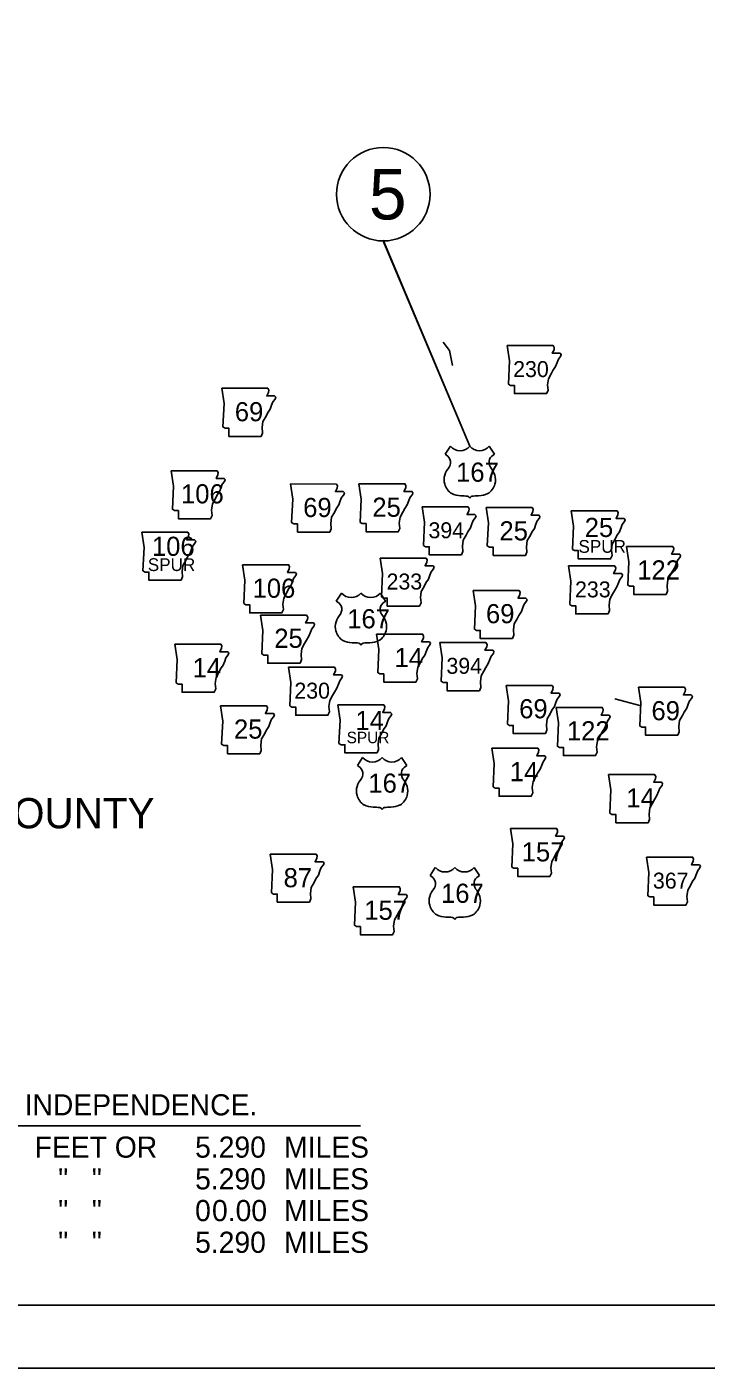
# Model space of a CAD drawing. Extents: x 840176 to 859715, y 1589036 to 1600368.
# Drawn here: x 849210 to 851907, y 1589036 to 1594363 of the extents above; entities that cross this region are included whole.
import ezdxf

# ---------------------------------------------------------------- set-up
doc = ezdxf.new("R2010")
doc.units = 0
for name, color, linetype in [('2', 7, 'Continuous'), ('6', 7, 'Continuous'), ('DSN_DRFT_Border', 7, 'Continuous'), ('SHET_Border-Text', 7, 'Continuous')]:
    doc.layers.add(name, color=color, linetype=linetype)

msp = doc.modelspace()

# ---------------------------------------------------------------- linework, layer by layer
at = {"layer": '2'}
msp.add_line((851545.1, 1591693.8), (851644.2, 1591667.9), dxfattribs=at)
msp.add_lwpolyline([(850863.7, 1593110.2), (850888.2, 1593076.9), (850900.7, 1593017.7)], dxfattribs=at)
for points in [[(851117.5, 1593096.8), (851126.6, 1593035.9), (851122.6, 1592943.5), (851130.7, 1592938.4), (851145.9, 1592938.4), (851145.9, 1592905.9), (851273.8, 1592905.9), (851279.9, 1592919.1), (851277.9, 1592940.4), (851280.9, 1592964.8), (851292.1, 1592984.1), (851299.2, 1592998.3), (851309.3, 1593013.5), (851315.4, 1593029.8), (851320.5, 1593043), (851329.6, 1593054.1), (851331.7, 1593061.2), (851327.6, 1593066.3), (851296.1, 1593066.3), (851303.3, 1593080.5), (851304.3, 1593089.7), (851300.1, 1593096.7)], [(849984.1, 1592927.2), (849993.3, 1592866.3), (849989.2, 1592773.9), (849997.3, 1592768.8), (850012.6, 1592768.8), (850012.6, 1592736.4), (850140.5, 1592736.4), (850146.6, 1592749.6), (850144.5, 1592770.9), (850147.6, 1592795.2), (850158.7, 1592814.5), (850165.8, 1592828.7), (850176, 1592844), (850182.1, 1592860.2), (850187.2, 1592873.4), (850196.3, 1592884.6), (850198.3, 1592891.7), (850194.3, 1592896.7), (850162.8, 1592896.7), (850169.9, 1592910.9), (850170.9, 1592920.1), (850166.7, 1592927.1)], [(849783.5, 1592600), (849792.6, 1592539.1), (849788.5, 1592446.8), (849796.7, 1592441.7), (849811.9, 1592441.7), (849811.9, 1592409.2), (849939.8, 1592409.2), (849945.9, 1592422.4), (849943.8, 1592443.7), (849946.9, 1592468.1), (849958.1, 1592487.4), (849965.2, 1592501.6), (849975.3, 1592516.8), (849981.4, 1592533), (849986.5, 1592546.2), (849995.6, 1592557.4), (849997.6, 1592564.5), (849993.6, 1592569.6), (849962.1, 1592569.6), (849969.2, 1592583.8), (849970.2, 1592592.9), (849966, 1592599.9)], [(850256.7, 1592547.2), (850265.9, 1592486.3), (850261.8, 1592393.9), (850269.9, 1592388.8), (850285.2, 1592388.8), (850285.2, 1592356.3), (850413.1, 1592356.3), (850419.1, 1592369.5), (850417.1, 1592390.9), (850420.2, 1592415.2), (850431.3, 1592434.5), (850438.4, 1592448.7), (850448.6, 1592463.9), (850454.7, 1592480.2), (850459.8, 1592493.4), (850468.9, 1592504.5), (850470.9, 1592511.6), (850466.9, 1592516.7), (850435.4, 1592516.7), (850442.5, 1592530.9), (850443.5, 1592540.1), (850439.3, 1592547.1)], [(850528.8, 1592548), (850537.9, 1592487.1), (850533.8, 1592394.7), (850542, 1592389.6), (850557.2, 1592389.6), (850557.2, 1592357.2), (850685.1, 1592357.2), (850691.2, 1592370.4), (850689.2, 1592391.7), (850692.2, 1592416), (850703.4, 1592435.3), (850710.5, 1592449.5), (850720.6, 1592464.8), (850726.7, 1592481), (850731.8, 1592494.2), (850740.9, 1592505.4), (850743, 1592512.5), (850738.9, 1592517.5), (850707.4, 1592517.5), (850714.5, 1592531.8), (850715.5, 1592540.9), (850711.3, 1592547.9)], [(850779.4, 1592456.2), (850788.5, 1592395.3), (850784.5, 1592302.9), (850792.6, 1592297.9), (850807.8, 1592297.9), (850807.8, 1592265.4), (850935.7, 1592265.4), (850941.8, 1592278.6), (850939.8, 1592299.9), (850942.8, 1592324.2), (850954, 1592343.5), (850961.1, 1592357.7), (850971.3, 1592373), (850977.4, 1592389.2), (850982.4, 1592402.4), (850991.6, 1592413.6), (850993.6, 1592420.7), (850989.5, 1592425.8), (850958.1, 1592425.8), (850965.2, 1592440), (850966.2, 1592449.1), (850962, 1592456.1)], [(851033.5, 1592454.2), (851042.6, 1592393.3), (851038.5, 1592300.9), (851046.6, 1592295.8), (851061.9, 1592295.8), (851061.9, 1592263.3), (851189.8, 1592263.3), (851195.9, 1592276.5), (851193.8, 1592297.8), (851196.9, 1592322.2), (851208, 1592341.5), (851215.2, 1592355.7), (851225.3, 1592370.9), (851231.4, 1592387.2), (851236.5, 1592400.4), (851245.6, 1592411.5), (851247.6, 1592418.6), (851243.6, 1592423.7), (851212.1, 1592423.7), (851219.2, 1592437.9), (851220.2, 1592447.1), (851216, 1592454.1)], [(851371.3, 1592440.7), (851380.4, 1592379.8), (851376.4, 1592287.4), (851384.5, 1592282.4), (851399.7, 1592282.4), (851399.7, 1592249.9), (851527.6, 1592249.9), (851533.7, 1592263.1), (851531.7, 1592284.4), (851534.7, 1592308.8), (851545.9, 1592328.1), (851553, 1592342.3), (851563.1, 1592357.5), (851569.2, 1592373.7), (851574.3, 1592386.9), (851583.4, 1592398.1), (851585.5, 1592405.2), (851581.4, 1592410.3), (851549.9, 1592410.3), (851557, 1592424.5), (851558.1, 1592433.6), (851553.9, 1592440.6)], [(849666.6, 1592355.7), (849675.7, 1592294.8), (849671.6, 1592202.4), (849679.8, 1592197.3), (849695, 1592197.3), (849695, 1592164.8), (849822.9, 1592164.8), (849829, 1592178), (849827, 1592199.3), (849830, 1592223.7), (849841.2, 1592243), (849848.3, 1592257.2), (849858.4, 1592272.4), (849864.5, 1592288.7), (849869.6, 1592301.9), (849878.7, 1592313), (849880.8, 1592320.1), (849876.7, 1592325.2), (849845.2, 1592325.2), (849852.3, 1592339.4), (849853.3, 1592348.6), (849849.1, 1592355.6)], [(851591.6, 1592299.1), (851600.8, 1592238.2), (851596.7, 1592145.8), (851604.8, 1592140.8), (851620, 1592140.8), (851620, 1592108.3), (851747.9, 1592108.3), (851754, 1592121.5), (851752, 1592142.8), (851755.1, 1592167.1), (851766.2, 1592186.4), (851773.3, 1592200.6), (851783.5, 1592215.9), (851789.6, 1592232.1), (851794.6, 1592245.3), (851803.8, 1592256.5), (851805.8, 1592263.6), (851801.7, 1592268.7), (851770.3, 1592268.7), (851777.4, 1592282.9), (851778.4, 1592292), (851774.2, 1592299)], [(850612.9, 1592252.6), (850622.1, 1592191.7), (850618, 1592099.4), (850626.1, 1592094.3), (850641.3, 1592094.3), (850641.3, 1592061.8), (850769.2, 1592061.8), (850775.3, 1592075), (850773.3, 1592096.3), (850776.3, 1592120.7), (850787.5, 1592140), (850794.6, 1592154.2), (850804.8, 1592169.4), (850810.9, 1592185.6), (850815.9, 1592198.8), (850825.1, 1592210), (850827.1, 1592217.1), (850823, 1592222.2), (850791.6, 1592222.2), (850798.7, 1592236.4), (850799.7, 1592245.5), (850795.5, 1592252.5)], [(850066.7, 1592226.1), (850075.9, 1592165.2), (850071.8, 1592072.9), (850079.9, 1592067.8), (850095.2, 1592067.8), (850095.2, 1592035.3), (850223.1, 1592035.3), (850229.1, 1592048.5), (850227.1, 1592069.8), (850230.2, 1592094.2), (850241.3, 1592113.5), (850248.4, 1592127.7), (850258.6, 1592142.9), (850264.7, 1592159.2), (850269.7, 1592172.4), (850278.9, 1592183.5), (850280.9, 1592190.6), (850276.9, 1592195.7), (850245.4, 1592195.7), (850252.5, 1592209.9), (850253.5, 1592219), (850249.3, 1592226.1)], [(851361.3, 1592221.9), (851370.4, 1592161), (851366.4, 1592068.6), (851374.5, 1592063.5), (851389.7, 1592063.5), (851389.7, 1592031), (851517.6, 1592031), (851523.7, 1592044.2), (851521.7, 1592065.5), (851524.7, 1592089.9), (851535.9, 1592109.2), (851543, 1592123.4), (851553.1, 1592138.6), (851559.2, 1592154.9), (851564.3, 1592168.1), (851573.4, 1592179.2), (851575.5, 1592186.3), (851571.4, 1592191.4), (851539.9, 1592191.4), (851547, 1592205.6), (851548.1, 1592214.8), (851543.8, 1592221.8)], [(850981.9, 1592124), (850991, 1592063.1), (850987, 1591970.7), (850995.1, 1591965.7), (851010.3, 1591965.7), (851010.3, 1591933.2), (851138.2, 1591933.2), (851144.3, 1591946.4), (851142.3, 1591967.7), (851145.3, 1591992), (851156.5, 1592011.3), (851163.6, 1592025.5), (851173.8, 1592040.8), (851179.9, 1592057), (851184.9, 1592070.2), (851194.1, 1592081.4), (851196.1, 1592088.5), (851192, 1592093.6), (851160.6, 1592093.6), (851167.7, 1592107.8), (851168.7, 1592116.9), (851164.5, 1592123.9)], [(850138.6, 1592025.8), (850147.7, 1591964.9), (850143.7, 1591872.5), (850151.8, 1591867.4), (850167, 1591867.4), (850167, 1591835), (850294.9, 1591835), (850301, 1591848.2), (850299, 1591869.5), (850302, 1591893.8), (850313.2, 1591913.1), (850320.3, 1591927.3), (850330.4, 1591942.6), (850336.5, 1591958.8), (850341.6, 1591972), (850350.7, 1591983.2), (850352.8, 1591990.3), (850348.7, 1591995.3), (850317.2, 1591995.3), (850324.4, 1592009.6), (850325.4, 1592018.7), (850321.2, 1592025.7)], [(850598.7, 1591951.2), (850607.9, 1591890.3), (850603.8, 1591797.9), (850611.9, 1591792.8), (850627.1, 1591792.8), (850627.1, 1591760.3), (850755, 1591760.3), (850761.1, 1591773.5), (850759.1, 1591794.8), (850762.1, 1591819.2), (850773.3, 1591838.5), (850780.4, 1591852.7), (850790.6, 1591867.9), (850796.7, 1591884.2), (850801.7, 1591897.4), (850810.9, 1591908.5), (850812.9, 1591915.6), (850808.8, 1591920.7), (850777.4, 1591920.7), (850784.5, 1591934.9), (850785.5, 1591944.1), (850781.3, 1591951.1)], [(850850.6, 1591917.1), (850859.8, 1591856.2), (850855.7, 1591763.8), (850863.8, 1591758.8), (850879.1, 1591758.8), (850879.1, 1591726.3), (851007, 1591726.3), (851013, 1591739.5), (851011, 1591760.8), (851014.1, 1591785.1), (851025.2, 1591804.4), (851032.3, 1591818.6), (851042.5, 1591833.9), (851048.6, 1591850.1), (851053.6, 1591863.3), (851062.8, 1591874.5), (851064.8, 1591881.6), (851060.8, 1591886.7), (851029.3, 1591886.7), (851036.4, 1591900.9), (851037.4, 1591910), (851033.2, 1591917)], [(849798.1, 1591910.9), (849807.2, 1591850), (849803.2, 1591757.6), (849811.3, 1591752.5), (849826.5, 1591752.5), (849826.5, 1591720.1), (849954.4, 1591720.1), (849960.5, 1591733.2), (849958.5, 1591754.6), (849961.5, 1591778.9), (849972.7, 1591798.2), (849979.8, 1591812.4), (849989.9, 1591827.7), (849996, 1591843.9), (850001.1, 1591857.1), (850010.2, 1591868.3), (850012.3, 1591875.4), (850008.2, 1591880.4), (849976.7, 1591880.4), (849983.8, 1591894.6), (849984.9, 1591903.8), (849980.7, 1591910.8)], [(850249.5, 1591819.5), (850258.6, 1591758.6), (850254.5, 1591666.2), (850262.6, 1591661.2), (850277.9, 1591661.2), (850277.9, 1591628.7), (850405.8, 1591628.7), (850411.9, 1591641.9), (850409.8, 1591663.2), (850412.9, 1591687.5), (850424, 1591706.8), (850431.2, 1591721), (850441.3, 1591736.3), (850447.4, 1591752.5), (850452.5, 1591765.7), (850461.6, 1591776.9), (850463.6, 1591784), (850459.6, 1591789.1), (850428.1, 1591789.1), (850435.2, 1591803.3), (850436.2, 1591812.4), (850432, 1591819.4)], [(851113, 1591746.9), (851122.1, 1591686), (851118, 1591593.6), (851126.1, 1591588.6), (851141.4, 1591588.6), (851141.4, 1591556.1), (851269.3, 1591556.1), (851275.4, 1591569.3), (851273.3, 1591590.6), (851276.4, 1591615), (851287.5, 1591634.2), (851294.7, 1591648.5), (851304.8, 1591663.7), (851310.9, 1591679.9), (851316, 1591693.1), (851325.1, 1591704.3), (851327.1, 1591711.4), (851323.1, 1591716.5), (851291.6, 1591716.5), (851298.7, 1591730.7), (851299.7, 1591739.8), (851295.5, 1591746.8)], [(851638.3, 1591739.8), (851647.5, 1591678.9), (851643.4, 1591586.5), (851651.5, 1591581.4), (851666.7, 1591581.4), (851666.7, 1591549), (851794.6, 1591549), (851800.7, 1591562.2), (851798.7, 1591583.5), (851801.7, 1591607.8), (851812.9, 1591627.1), (851820, 1591641.3), (851830.2, 1591656.6), (851836.3, 1591672.8), (851841.3, 1591686), (851850.5, 1591697.2), (851852.5, 1591704.3), (851848.4, 1591709.3), (851817, 1591709.3), (851824.1, 1591723.6), (851825.1, 1591732.7), (851820.9, 1591739.7)], [(849978.9, 1591666.6), (849988, 1591605.7), (849983.9, 1591513.4), (849992.1, 1591508.3), (850007.3, 1591508.3), (850007.3, 1591475.8), (850135.2, 1591475.8), (850141.3, 1591489), (850139.3, 1591510.3), (850142.3, 1591534.7), (850153.5, 1591554), (850160.6, 1591568.2), (850170.7, 1591583.4), (850176.8, 1591599.6), (850181.9, 1591612.8), (850191, 1591624), (850193.1, 1591631.1), (850189, 1591636.2), (850157.5, 1591636.2), (850164.6, 1591650.4), (850165.6, 1591659.5), (850161.4, 1591666.5)], [(850444.6, 1591670.1), (850453.8, 1591609.2), (850449.7, 1591516.8), (850457.8, 1591511.8), (850473, 1591511.8), (850473, 1591479.3), (850600.9, 1591479.3), (850607, 1591492.5), (850605, 1591513.8), (850608.1, 1591538.2), (850619.2, 1591557.5), (850626.3, 1591571.7), (850636.5, 1591586.9), (850642.6, 1591603.1), (850647.6, 1591616.3), (850656.8, 1591627.5), (850658.8, 1591634.6), (850654.7, 1591639.7), (850623.3, 1591639.7), (850630.4, 1591653.9), (850631.4, 1591663), (850627.2, 1591670)], [(851312, 1591659.1), (851321.1, 1591598.2), (851317.1, 1591505.8), (851325.2, 1591500.8), (851340.4, 1591500.8), (851340.4, 1591468.3), (851468.3, 1591468.3), (851474.4, 1591481.5), (851472.4, 1591502.8), (851475.4, 1591527.2), (851486.6, 1591546.4), (851493.7, 1591560.7), (851503.8, 1591575.9), (851509.9, 1591592.1), (851515, 1591605.3), (851524.1, 1591616.5), (851526.2, 1591623.6), (851522.1, 1591628.7), (851490.6, 1591628.7), (851497.7, 1591642.9), (851498.8, 1591652), (851494.6, 1591659)], [(851056.5, 1591497.8), (851065.7, 1591436.9), (851061.6, 1591344.5), (851069.7, 1591339.4), (851085, 1591339.4), (851085, 1591306.9), (851212.9, 1591306.9), (851219, 1591320.1), (851216.9, 1591341.5), (851220, 1591365.8), (851231.1, 1591385.1), (851238.2, 1591399.3), (851248.4, 1591414.5), (851254.5, 1591430.8), (851259.6, 1591444), (851268.7, 1591455.1), (851270.7, 1591462.3), (851266.7, 1591467.3), (851235.2, 1591467.3), (851242.3, 1591481.5), (851243.3, 1591490.7), (851239.1, 1591497.7)], [(851520.2, 1591392.9), (851529.4, 1591331.9), (851525.3, 1591239.6), (851533.4, 1591234.5), (851548.7, 1591234.5), (851548.7, 1591202), (851676.6, 1591202), (851682.6, 1591215.2), (851680.6, 1591236.5), (851683.7, 1591260.9), (851694.8, 1591280.2), (851701.9, 1591294.4), (851712.1, 1591309.6), (851718.2, 1591325.9), (851723.2, 1591339.1), (851732.4, 1591350.2), (851734.4, 1591357.3), (851730.4, 1591362.4), (851698.9, 1591362.4), (851706, 1591376.6), (851707, 1591385.7), (851702.8, 1591392.8)], [(851130.7, 1591179.3), (851139.9, 1591118.4), (851135.8, 1591026), (851143.9, 1591020.9), (851159.2, 1591020.9), (851159.2, 1590988.5), (851287.1, 1590988.5), (851293.1, 1591001.7), (851291.1, 1591023), (851294.2, 1591047.3), (851305.3, 1591066.6), (851312.4, 1591080.8), (851322.6, 1591096.1), (851328.7, 1591112.3), (851333.7, 1591125.5), (851342.9, 1591136.7), (851344.9, 1591143.8), (851340.9, 1591148.8), (851309.4, 1591148.8), (851316.5, 1591163.1), (851317.5, 1591172.2), (851313.3, 1591179.2)], [(850176, 1591077.2), (850185.2, 1591016.3), (850181.1, 1590923.9), (850189.2, 1590918.8), (850204.5, 1590918.8), (850204.5, 1590886.4), (850332.4, 1590886.4), (850338.4, 1590899.6), (850336.4, 1590920.9), (850339.5, 1590945.2), (850350.6, 1590964.5), (850357.7, 1590978.7), (850367.9, 1590994), (850374, 1591010.2), (850379, 1591023.4), (850388.2, 1591034.6), (850390.2, 1591041.7), (850386.2, 1591046.7), (850354.7, 1591046.7), (850361.8, 1591061), (850362.8, 1591070.1), (850358.6, 1591077.1)], [(851670.6, 1591065.3), (851679.7, 1591004.4), (851675.6, 1590912), (851683.8, 1590907), (851699, 1590907), (851699, 1590874.5), (851826.9, 1590874.5), (851833, 1590887.7), (851830.9, 1590909), (851834, 1590933.4), (851845.2, 1590952.6), (851852.3, 1590966.9), (851862.4, 1590982.1), (851868.5, 1590998.3), (851873.6, 1591011.5), (851882.7, 1591022.7), (851884.7, 1591029.8), (851880.7, 1591034.9), (851849.2, 1591034.9), (851856.3, 1591049.1), (851857.3, 1591058.2), (851853.1, 1591065.2)], [(850506.2, 1590947.7), (850515.4, 1590886.7), (850511.3, 1590794.4), (850519.4, 1590789.3), (850534.6, 1590789.3), (850534.6, 1590756.8), (850662.5, 1590756.8), (850668.6, 1590770), (850666.6, 1590791.3), (850669.7, 1590815.7), (850680.8, 1590835), (850687.9, 1590849.2), (850698.1, 1590864.4), (850704.2, 1590880.7), (850709.2, 1590893.9), (850718.4, 1590905), (850720.4, 1590912.1), (850716.3, 1590917.2), (850684.9, 1590917.2), (850692, 1590931.4), (850693, 1590940.5), (850688.8, 1590947.6)]]:
    msp.add_lwpolyline(points, close=True, dxfattribs=at)
at = {"layer": '6'}
for p, q in [((850891.7, 1592697.3), (850871, 1592665.2)), ((851046.2, 1592697.3), (851066.9, 1592665.2)), ((850459.7, 1592113.8), (850438.9, 1592081.7)), ((850614.1, 1592113.8), (850634.9, 1592081.7)), ((850543.6, 1591460.8), (850522.8, 1591428.7)), ((850698, 1591460.8), (850718.8, 1591428.7)), ((850832.1, 1591024.1), (850811.3, 1590992)), ((850986.5, 1591024.1), (851007.3, 1590992))]:
    msp.add_line(p, q, dxfattribs=at)
for centre, radius, start, end in [((850843.8, 1592618.6), 54, 30.7809, 59.9883), ((850930.4, 1592729.9), 50.5, 220.075, 319.6701), ((851007.5, 1592729.9), 50.5, 220.3299, 319.925), ((851094.1, 1592618.6), 54, 120.0117, 149.2191), ((850952.4, 1592557), 86.3, 138.9565, 162.6913), ((850855.7, 1592632.8), 37, 328.8105, 21.2108), ((851082.2, 1592632.8), 37, 158.7892, 211.1895), ((850985.5, 1592557), 86.3, 17.3087, 41.0435), ((850923.9, 1592564), 57, 160.9576, 197.3819), ((851014, 1592564), 57, 342.6181, 19.0424), ((850933.2, 1592564.2), 66, 195.1074, 237.1312), ((850934.5, 1592585), 84.7, 244.0771, 269.5779), ((850936.4, 1592345.1), 155.2, 81.1942, 90.9539), ((850955.8, 1592484.2), 14.9, 28.0342, 72.9864), ((850982.1, 1592484.2), 14.9, 107.0136, 151.9658), ((851001.5, 1592345.1), 155.2, 89.0461, 98.8058), ((851003.4, 1592585), 84.7, 270.4221, 295.9229), ((851004.7, 1592564.2), 66, 302.8688, 344.8926), ((850411.8, 1592035.1), 54, 30.7809, 59.9883), ((850498.4, 1592146.4), 50.5, 220.075, 319.6701), ((850575.5, 1592146.4), 50.5, 220.3299, 319.925), ((850662, 1592035.1), 54, 120.0117, 149.2191), ((850520.4, 1591973.5), 86.3, 138.9565, 162.6913), ((850423.7, 1592049.3), 37, 328.8105, 21.2108), ((850650.2, 1592049.3), 37, 158.7892, 211.1895), ((850553.4, 1591973.5), 86.3, 17.3087, 41.0435), ((850491.9, 1591980.5), 57, 160.9576, 197.3819), ((850581.9, 1591980.5), 57, 342.6181, 19.0424), ((850501.2, 1591980.7), 66, 195.1074, 237.1312), ((850502.4, 1592001.5), 84.7, 244.0771, 269.5779), ((850504.4, 1591761.6), 155.2, 81.1942, 90.9539), ((850523.8, 1591900.7), 14.9, 28.0342, 72.9864), ((850550, 1591900.7), 14.9, 107.0136, 151.9658), ((850569.5, 1591761.6), 155.2, 89.0461, 98.8058), ((850571.4, 1592001.5), 84.7, 270.4221, 295.9229), ((850572.6, 1591980.7), 66, 302.8688, 344.8926), ((850582.3, 1591493.4), 50.5, 220.075, 319.6701), ((850659.4, 1591493.4), 50.5, 220.3299, 319.925), ((850495.7, 1591382.1), 54, 30.7809, 59.9883), ((850507.6, 1591396.3), 37, 328.8105, 21.2108), ((850734.1, 1591396.3), 37, 158.7892, 211.1895), ((850745.9, 1591382.1), 54, 120.0117, 149.2191), ((850575.8, 1591327.5), 57, 160.9576, 197.3819), ((850604.3, 1591320.5), 86.3, 138.9565, 162.6913), ((850637.3, 1591320.5), 86.3, 17.3087, 41.0435), ((850665.8, 1591327.5), 57, 342.6181, 19.0424), ((850585.1, 1591327.7), 66, 195.1074, 237.1312), ((850586.3, 1591348.5), 84.7, 244.0771, 269.5779), ((850655.3, 1591348.5), 84.7, 270.4221, 295.9229), ((850656.5, 1591327.7), 66, 302.8688, 344.8926), ((850588.3, 1591108.6), 155.2, 81.1942, 90.9539), ((850607.7, 1591247.7), 14.9, 28.0342, 72.9864), ((850634, 1591247.7), 14.9, 107.0136, 151.9658), ((850653.4, 1591108.6), 155.2, 89.0461, 98.8058), ((850870.8, 1591056.7), 50.5, 220.075, 319.6701), ((850947.9, 1591056.7), 50.5, 220.3299, 319.925), ((850784.2, 1590945.4), 54, 30.7809, 59.9883), ((850796.1, 1590959.6), 37, 328.8105, 21.2108), ((851022.6, 1590959.6), 37, 158.7892, 211.1895), ((851034.4, 1590945.4), 54, 120.0117, 149.2191), ((850864.3, 1590890.9), 57, 160.9576, 197.3819), ((850892.8, 1590883.8), 86.3, 138.9565, 162.6913), ((850925.8, 1590883.8), 86.3, 17.3087, 41.0435), ((850954.3, 1590890.9), 57, 342.6181, 19.0424), ((850873.6, 1590891), 66, 195.1074, 237.1312), ((850945, 1590891), 66, 302.8688, 344.8926), ((850874.8, 1590911.8), 84.7, 244.0771, 269.5779), ((850876.8, 1590671.9), 155.2, 81.1942, 90.9539), ((850896.2, 1590811), 14.9, 28.0342, 72.9864), ((850922.5, 1590811), 14.9, 107.0136, 151.9658), ((850941.9, 1590671.9), 155.2, 89.0461, 98.8058), ((850943.8, 1590911.8), 84.7, 270.4221, 295.9229)]:
    msp.add_arc(centre, radius, start, end, dxfattribs=at)
at = {"layer": 'DSN_DRFT_Border'}
msp.add_line((846815.5, 1589997.6), (850535.5, 1589997.6), dxfattribs=at)
msp.add_lwpolyline([(840175.5, 1600035.6), (840175.5, 1589035.6), (857175.5, 1589035.6), (857175.5, 1600035.6)], close=True, dxfattribs=at)
for points in [[(850623.9, 1593514.9), (850969, 1592697.1)], [(850969, 1592697.1), (850627, 1593512.4)]]:
    msp.add_lwpolyline(points, dxfattribs=at)
msp.add_circle((850625.5, 1593697.9), 185.5, dxfattribs=at)
at = {"layer": 'SHET_Border-Text'}
for points in [[(840175.5, 1589035.6), (857175.5, 1589035.6), (857175.5, 1600035.6), (840175.5, 1600035.6)], [(840425.5, 1589285.6), (856925.5, 1589285.6), (856925.5, 1599785.6), (840425.5, 1599785.6)]]:
    msp.add_lwpolyline(points, close=True, dxfattribs=at)

# ---------------------------------------------------------------- texts
at = {"layer": '2'}
for s, height, p in [('230', 63.36, (851141, 1592971.8)), ('69', 76.03, (850036.1, 1592796.3)), ('106', 76.03, (849822.5, 1592470.1)), ('69', 76.03, (850307.6, 1592415.9)), ('25', 76.03, (850582.1, 1592417)), ('394', 63.36, (850805, 1592331.7)), ('25', 76.03, (851086.7, 1592323.2)), ('25', 76.03, (851425.1, 1592336.6)), ('106', 76.03, (849707.1, 1592261.7)), ('SPUR', 50.69, (851400.3, 1592273.9)), ('SPUR', 50.69, (849690.7, 1592201.4)), ('122', 76.03, (851633.7, 1592167.8)), ('233', 63.36, (850638.5, 1592128.1)), ('106', 76.03, (850106.7, 1592095.3)), ('233', 63.36, (851386.6, 1592096.9)), ('69', 76.03, (851033.2, 1591994.1)), ('25', 76.03, (850192.8, 1591896.4)), ('14', 76.03, (850670.1, 1591819.8)), ('14', 76.03, (849868.6, 1591779.6)), ('394', 63.36, (850876.2, 1591793.3)), ('230', 63.36, (850272.5, 1591694.7)), ('14', 76.03, (850514.9, 1591569.9)), ('69', 76.03, (851164.9, 1591616.6)), ('69', 76.03, (851690.1, 1591608.8)), ('25', 76.03, (850032.7, 1591535.9)), ('122', 76.03, (851354.5, 1591529)), ('SPUR', 45.62, (850480.1, 1591517.6)), ('14', 76.03, (851127.9, 1591366.7)), ('14', 76.03, (851590.5, 1591262.7)), ('157', 76.03, (851175, 1591048.3)), ('87', 76.03, (850229.8, 1590945.6)), ('367', 63.36, (851695.9, 1590940.2)), ('157', 76.03, (850550.1, 1590816.4))]:
    msp.add_text(s, height=height, dxfattribs=at).set_placement(p)
at = {"layer": '6'}
for p in [(850914.6, 1592556.2), (850482.4, 1591973.9), (850566.3, 1591321.3), (850854.8, 1590883.7)]:
    msp.add_text('167', height=76.03, dxfattribs=at).set_placement(p)
at = {"layer": 'DSN_DRFT_Border'}
for s, height, p in [('5', 200.4, (850568.7, 1593597.8)), ('INDEPENDENCE COUNTY', 120, (847720.2, 1591179.8)), ('NEWTON. VAN BUREN. FAULKNER. INDEPENDENCE. ', 84, (847260.6, 1590039.6)), ('FEET OR', 84, (849241.3, 1589871.6)), ('5.290 ', 84, (849878.5, 1589871.6)), ('MILES', 84, (850231.7, 1589871.6)), ('   "   "', 84, (849241.3, 1589745.6)), ('5.290 ', 84, (849878.5, 1589745.6)), ('MILES', 84, (850231.7, 1589745.6)), ('   "   "', 84, (849241.3, 1589619.6)), ('0', 84, (849878.5, 1589619.6)), ('0.00 ', 84, (849945.5, 1589619.6)), ('MILES', 84, (850231.7, 1589619.6)), ('   "   "', 84, (849241.3, 1589493.6)), ('5.290 ', 84, (849878.5, 1589493.6)), ('MILES', 84, (850231.7, 1589493.6))]:
    msp.add_text(s, height=height, dxfattribs=at).set_placement(p)

doc.saveas('drawing.dxf')
